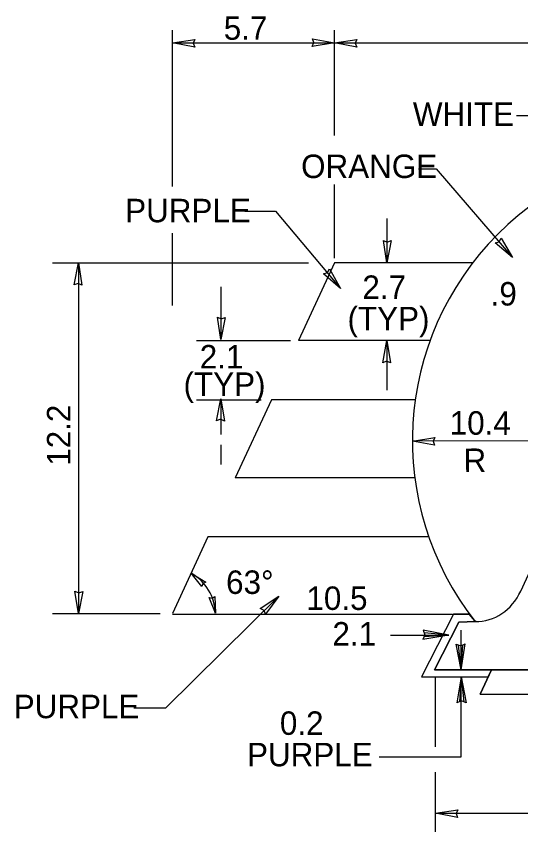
# Model space of a CAD drawing. Extents: x 10268197 to 10269179, y 2141503 to 2142677.
# Drawn here: x 10268672.11 to 10268684.39, y 2142078.08 to 2142097.94 of the extents above; entities that cross this region are included whole.
import ezdxf

# ---------------------------------------------------------------- set-up
doc = ezdxf.new("R2010")
doc.units = 0
doc.layers.add('Default', color=7, linetype='Continuous')

msp = doc.modelspace()

# ---------------------------------------------------------------- linework, layer by layer
at = {"layer": 'Default'}
for p, q in [((10268675.91, 2142093.801), (10268675.91, 2142097.608)), ((10268679.858, 2142095.039), (10268679.858, 2142097.608)), ((10268675.91, 2142097.295), (10268679.858, 2142097.295)), ((10268679.858, 2142097.295), (10268720.621, 2142097.295)), ((10268679.858, 2142092.049), (10268679.858, 2142093.843)), ((10268681.133, 2142093.014), (10268681.133, 2142091.94)), ((10268675.91, 2142090.896), (10268675.91, 2142092.66)), ((10268672.986, 2142091.94), (10268679.223, 2142091.94)), ((10268673.619, 2142091.94), (10268673.619, 2142087.652)), ((10268679.858, 2142091.94), (10268678.981, 2142090.041)), ((10268683.222, 2142091.94), (10268679.858, 2142091.94)), ((10268677.089, 2142091.349), (10268677.089, 2142090.068)), ((10268684.389, 2142083.937), (10268687.785, 2142091.349)), ((10268676.496, 2142090.041), (10268678.78, 2142090.041)), ((10268682.181, 2142090.041), (10268678.981, 2142090.041)), ((10268681.133, 2142090.041), (10268681.133, 2142088.834)), ((10268677.089, 2142088.627), (10268677.089, 2142087.756)), ((10268676.496, 2142088.6), (10268678.067, 2142088.6)), ((10268678.317, 2142088.6), (10268677.439, 2142086.701)), ((10268681.823, 2142088.6), (10268678.317, 2142088.6)), ((10268673.619, 2142087.652), (10268673.619, 2142083.391)), ((10268677.089, 2142087.502), (10268677.089, 2142087.025)), ((10268688.878, 2142087.607), (10268681.752, 2142087.596)), ((10268681.811, 2142086.701), (10268677.439, 2142086.701)), ((10268676.774, 2142085.261), (10268675.91, 2142083.391)), ((10268682.131, 2142085.261), (10268676.774, 2142085.261)), ((10268675.744, 2142081.096), (10268678.502, 2142083.817)), ((10268672.986, 2142083.391), (10268675.607, 2142083.391)), ((10268675.91, 2142083.379), (10268682.725, 2142083.379)), ((10268682.751, 2142083.379), (10268681.971, 2142081.846)), ((10268682.751, 2142083.379), (10268683.146, 2142083.379)), ((10268682.879, 2142083.183), (10268682.288, 2142082.021)), ((10268683.282, 2142083.195), (10268682.879, 2142083.183)), ((10268681.216, 2142082.868), (10268682.641, 2142082.868)), ((10268682.058, 2142082.873), (10268682.009, 2142082.763)), ((10268682.641, 2142082.868), (10268682.009, 2142082.763)), ((10268682.641, 2142082.868), (10268682.011, 2142082.985)), ((10268682.011, 2142082.985), (10268682.058, 2142082.873)), ((10268682.641, 2142082.868), (10268682.036, 2142082.926)), ((10268682.641, 2142082.868), (10268682.036, 2142082.821)), ((10268682.939, 2142082.021), (10268682.939, 2142082.989)), ((10268682.939, 2142082.078), (10268682.939, 2142082.698)), ((10268682.939, 2142082.021), (10268682.816, 2142082.649)), ((10268682.816, 2142082.649), (10268682.929, 2142082.603)), ((10268682.939, 2142082.021), (10268682.876, 2142082.625)), ((10268682.929, 2142082.603), (10268683.039, 2142082.653)), ((10268682.939, 2142082.021), (10268683.039, 2142082.653)), ((10268682.939, 2142082.021), (10268682.981, 2142082.626)), ((10268682.288, 2142082.021), (10268691.34, 2142082.021)), ((10268683.405, 2142081.431), (10268683.678, 2142082.021)), ((10268683.678, 2142082.021), (10268683.405, 2142081.431)), ((10268683.62, 2142081.896), (10268683.678, 2142082.021)), ((10268691.34, 2142082.021), (10268683.678, 2142082.021)), ((10268681.971, 2142081.846), (10268683.597, 2142081.846)), ((10268682.313, 2142080.146), (10268682.313, 2142081.836)), ((10268682.939, 2142081.846), (10268682.838, 2142081.213)), ((10268682.939, 2142081.846), (10268682.896, 2142081.24)), ((10268682.939, 2142079.897), (10268682.939, 2142081.846)), ((10268682.939, 2142081.846), (10268683.061, 2142081.217)), ((10268682.939, 2142081.846), (10268683.002, 2142081.241)), ((10268683.405, 2142081.431), (10268691.866, 2142081.431)), ((10268683.405, 2142081.431), (10268691.866, 2142081.431)), ((10268674.969, 2142081.096), (10268675.744, 2142081.096)), ((10268682.948, 2142081.263), (10268682.838, 2142081.213)), ((10268683.061, 2142081.217), (10268682.948, 2142081.263)), ((10268680.943, 2142079.897), (10268682.939, 2142079.897)), ((10268682.313, 2142078.077), (10268682.313, 2142079.527)), ((10268682.313, 2142078.528), (10268691.34, 2142078.528))]:
    msp.add_line(p, q, dxfattribs=at)
for points in [[(10268675.91, 2142097.295), (10268676.454, 2142097.38), (10268676.413, 2142097.287), (10268676.45, 2142097.19)], [(10268679.858, 2142097.295), (10268679.314, 2142097.209), (10268679.355, 2142097.302), (10268679.318, 2142097.399)], [(10268679.858, 2142097.295), (10268680.402, 2142097.38), (10268680.361, 2142097.287), (10268680.399, 2142097.19)], [(10268681.133, 2142091.94), (10268681.047, 2142092.484), (10268681.14, 2142092.443), (10268681.237, 2142092.48)], [(10268684.186, 2142092.065), (10268683.767, 2142092.421), (10268683.864, 2142092.451), (10268683.913, 2142092.542)], [(10268673.619, 2142091.94), (10268673.705, 2142091.396), (10268673.611, 2142091.437), (10268673.514, 2142091.399)], [(10268680.005, 2142091.312), (10268679.589, 2142091.673), (10268679.687, 2142091.701), (10268679.737, 2142091.792)], [(10268677.089, 2142090.068), (10268677.003, 2142090.612), (10268677.096, 2142090.571), (10268677.193, 2142090.608)], [(10268681.133, 2142090.041), (10268681.218, 2142089.497), (10268681.125, 2142089.538), (10268681.028, 2142089.501)], [(10268677.089, 2142088.627), (10268677.174, 2142088.083), (10268677.081, 2142088.124), (10268676.984, 2142088.087)], [(10268681.752, 2142087.596), (10268682.296, 2142087.682), (10268682.256, 2142087.589), (10268682.293, 2142087.492)], [(10268676.366, 2142084.373), (10268676.721, 2142084.159), (10268676.652, 2142084.125), (10268676.626, 2142084.052)], [(10268673.619, 2142083.391), (10268673.533, 2142083.934), (10268673.626, 2142083.894), (10268673.723, 2142083.931)], [(10268676.954, 2142083.399), (10268676.804, 2142083.783), (10268676.879, 2142083.768), (10268676.944, 2142083.811)], [(10268678.502, 2142083.817), (10268678.175, 2142083.374), (10268678.139, 2142083.469), (10268678.044, 2142083.512)], [(10268683.134, 2142083.379), (10268682.751, 2142083.379), (10268681.971, 2142081.846), (10268683.597, 2142081.846), (10268683.678, 2142082.021), (10268682.288, 2142082.021), (10268682.879, 2142083.183), (10268683.293, 2142083.195), (10268683.275, 2142083.215)], [(10268682.313, 2142078.528), (10268682.857, 2142078.613), (10268682.816, 2142078.52), (10268682.853, 2142078.423)]]:
    msp.add_lwpolyline(points, close=True, dxfattribs=at)
for points in [[(10268684.287, 2142095.528), (10268684.754, 2142095.528), (10268688.109, 2142092.378)], [(10268681.901, 2142094.224), (10268682.331, 2142094.224), (10268684.186, 2142092.065)], [(10268677.674, 2142093.199), (10268678.418, 2142093.199), (10268680.005, 2142091.312)], [(10268679.998, 2142091.313), (10268680.005, 2142091.312), (10268679.998, 2142091.317), (10268680.001, 2142091.315), (10268680.001, 2142091.315), (10268680.001, 2142091.315), (10268680.003, 2142091.313), (10268680.001, 2142091.315), (10268680.003, 2142091.313), (10268679.998, 2142091.315), (10268680.001, 2142091.313), (10268679.998, 2142091.313), (10268679.998, 2142091.313), (10268680.001, 2142091.315), (10268679.998, 2142091.317)], [(10268679.998, 2142091.313), (10268680.005, 2142091.312), (10268679.998, 2142091.317), (10268680.001, 2142091.315), (10268680.001, 2142091.315), (10268680.001, 2142091.315), (10268680.003, 2142091.313), (10268680.001, 2142091.315), (10268680.003, 2142091.313), (10268679.998, 2142091.315), (10268680.001, 2142091.313), (10268679.998, 2142091.313), (10268679.998, 2142091.313), (10268680.001, 2142091.315), (10268679.998, 2142091.317)], [(10268679.998, 2142091.313), (10268680.005, 2142091.312), (10268679.998, 2142091.317), (10268680.001, 2142091.315), (10268680.001, 2142091.315), (10268680.001, 2142091.315), (10268680.003, 2142091.313), (10268680.001, 2142091.315), (10268680.003, 2142091.313), (10268679.998, 2142091.315), (10268680.001, 2142091.313), (10268679.998, 2142091.313), (10268679.998, 2142091.313), (10268680.001, 2142091.315), (10268679.998, 2142091.317)]]:
    msp.add_lwpolyline(points, dxfattribs=at)
for centre, radius, start, end in [((10268688.878, 2142087.607), 7.125, 51.9618, 218.2529), ((10268675.819, 2142083.381), 1.132, 0.8256, 61.0937)]:
    msp.add_arc(centre, radius, start, end, dxfattribs=at)
msp.add_ellipse((10268683.305, 2142084.553), major_axis=(0, 1.356), ratio=0.897229, start_param=3.121696, end_param=4.241135, dxfattribs=at)

# ---------------------------------------------------------------- texts
for s, p in [('5.7', (10268677.158, 2142097.372)), ('WHITE', (10268681.764, 2142095.273)), ('ORANGE', (10268679.042, 2142094.003)), ('PURPLE', (10268674.758, 2142092.925)), ('2.7', (10268680.534, 2142091.058)), ('.9', (10268683.657, 2142090.897)), ('(TYP)', (10268680.172, 2142090.292)), ('2.1', (10268676.573, 2142089.363)), ('(TYP)', (10268676.179, 2142088.695)), ('63°', (10268677.215, 2142083.87)), ('10.5', (10268679.171, 2142083.48)), ('2.1', (10268679.805, 2142082.612)), ('PURPLE', (10268672.044, 2142080.842)), ('0.2', (10268678.525, 2142080.436)), ('PURPLE', (10268677.725, 2142079.67))]:
    msp.add_text(s, height=0.5717, dxfattribs=at).set_placement(p)
for s, height, rotation, p in [('12.2', 0.5717, 90, (10268673.424, 2142086.993)), ('10.4', 0.5717, 359.5763, (10268682.659, 2142087.754)), ('R', 0.572, 0.3852, (10268682.999, 2142086.84))]:
    msp.add_text(s, height=height, rotation=rotation, dxfattribs=at).set_placement(p)

doc.saveas('drawing.dxf')
